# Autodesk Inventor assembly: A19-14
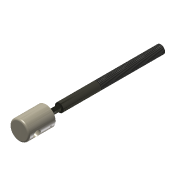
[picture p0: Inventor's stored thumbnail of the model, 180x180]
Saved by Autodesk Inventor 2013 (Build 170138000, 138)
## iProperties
Created: 2008-07
Part Number: A19-14
Document SubType Name: Assembly
Designer: y-shimohigashi
Stock Number: A19-14
Author: y-shimohigashi
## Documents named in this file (3)
- C:\Users\t-komatsu\Desktop\新しいフォルダー\Inventor2013基礎コース\練習問題-19\A19-14.iam
- C:\Users\t-komatsu\Desktop\新しいフォルダー\Inventor2013基礎コース\練習問題-19\P19-5締付ネジ.ipt
- C:\Users\t-komatsu\Desktop\新しいフォルダー\Inventor2013基礎コース\練習問題-19\P19-7ハンドル取付棒.ipt
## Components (2 placed, 2 different names)
1. P19-5締付ネジ:1
2. P19-7ハンドル取付棒:1
